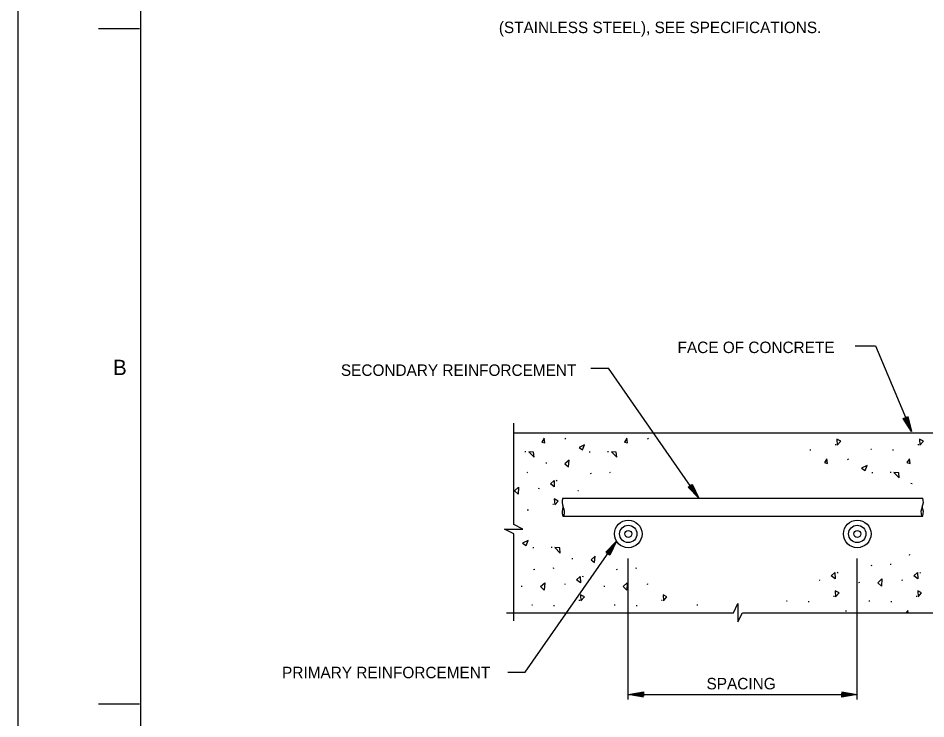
# Model space of a CAD drawing. Extents: x 22369.62 to 22373.29, y 22369.62 to 22372.46.
# Drawn here: x 22369.621 to 22370.546, y 22370.335 to 22371.049 of the extents above; entities that cross this region are included whole.
import ezdxf

# ---------------------------------------------------------------- set-up
doc = ezdxf.new("R2010")
doc.units = 0
for name, color, linetype in [('Default', 7, 'Continuous'), ('Level 1', 7, 'Continuous'), ('Level 10', 7, 'Continuous'), ('Level 2', 7, 'Continuous'), ('Level 22', 7, 'Continuous'), ('Level 4', 7, 'Continuous'), ('Level 7', 7, 'Continuous'), ('Level 8', 7, 'Continuous'), ('Level 9', 7, 'Continuous')]:
    doc.layers.add(name, color=color, linetype=linetype)

msp = doc.modelspace()

# ---------------------------------------------------------------- linework, layer by layer
at = {"layer": 'Default'}
for p, q in [((22370.1793, 22370.62059), (22370.1783, 22370.62009)), ((22370.26346, 22370.62059), (22370.26246, 22370.62009)), ((22370.42905, 22370.6087), (22370.42792, 22370.6087)), ((22370.45469, 22370.61428), (22370.45386, 22370.61434)), ((22370.4908, 22370.6094), (22370.48996, 22370.60955)), ((22370.51321, 22370.6087), (22370.51209, 22370.6087)), ((22370.53886, 22370.61428), (22370.53803, 22370.61434)), ((22370.13871, 22370.60715), (22370.13765, 22370.60715)), ((22370.20421, 22370.60676), (22370.20309, 22370.60676)), ((22370.22288, 22370.60715), (22370.22182, 22370.60715)), ((22370.46721, 22370.59959), (22370.46621, 22370.59909)), ((22370.15992, 22370.59551), (22370.15884, 22370.5957)), ((22370.14036, 22370.58607), (22370.13955, 22370.58576)), ((22370.20511, 22370.58495), (22370.20398, 22370.58463)), ((22370.22453, 22370.58607), (22370.22371, 22370.58576)), ((22370.49213, 22370.58576), (22370.491, 22370.58576)), ((22370.5108, 22370.58615), (22370.50973, 22370.58615)), ((22370.17053, 22370.57724), (22370.16959, 22370.5778)), ((22370.532, 22370.57451), (22370.53092, 22370.5747)), ((22370.15238, 22370.56949), (22370.15148, 22370.5699)), ((22370.19236, 22370.56749), (22370.19144, 22370.5674)), ((22370.16678, 22370.5533), (22370.16594, 22370.55336)), ((22370.14113, 22370.54772), (22370.14, 22370.54772)), ((22370.14668, 22370.5092), (22370.14556, 22370.5092)), ((22370.16535, 22370.50959), (22370.16429, 22370.50959)), ((22370.18656, 22370.49795), (22370.18547, 22370.49813)), ((22370.5302, 22370.50194), (22370.52912, 22370.50212)), ((22370.16699, 22370.48851), (22370.16618, 22370.4882)), ((22370.25116, 22370.48851), (22370.25035, 22370.4882)), ((22370.49122, 22370.49137), (22370.4901, 22370.49106)), ((22370.51064, 22370.4925), (22370.50983, 22370.49219)), ((22370.14758, 22370.48738), (22370.14645, 22370.48707)), ((22370.19716, 22370.47968), (22370.19622, 22370.48024)), ((22370.23174, 22370.48738), (22370.23062, 22370.48707)), ((22370.45664, 22370.48366), (22370.4557, 22370.48423)), ((22370.54081, 22370.48366), (22370.53987, 22370.48423)), ((22370.13483, 22370.46993), (22370.13391, 22370.46984)), ((22370.17901, 22370.47193), (22370.17812, 22370.47234)), ((22370.21899, 22370.46993), (22370.21808, 22370.46984)), ((22370.26318, 22370.47193), (22370.26229, 22370.47234)), ((22370.43849, 22370.47591), (22370.4376, 22370.47633)), ((22370.47847, 22370.47391), (22370.47756, 22370.47383)), ((22370.52266, 22370.47591), (22370.52176, 22370.47633)), ((22370.19341, 22370.45574), (22370.19258, 22370.4558)), ((22370.27758, 22370.45574), (22370.27674, 22370.4558)), ((22370.40483, 22370.45485), (22370.40399, 22370.455)), ((22370.42724, 22370.45414), (22370.42612, 22370.45414)), ((22370.45289, 22370.45973), (22370.45206, 22370.45979)), ((22370.48899, 22370.45485), (22370.48816, 22370.455)), ((22370.51141, 22370.45414), (22370.51029, 22370.45414)), ((22370.53706, 22370.45973), (22370.53622, 22370.45979)), ((22370.14535, 22370.45086), (22370.14451, 22370.45101)), ((22370.16776, 22370.45015), (22370.16664, 22370.45015)), ((22370.22951, 22370.45086), (22370.22868, 22370.45101)), ((22370.25193, 22370.45015), (22370.25081, 22370.45015)), ((22370.31368, 22370.45086), (22370.31285, 22370.45101)), ((22370.46541, 22370.44504), (22370.46441, 22370.44454))]:
    msp.add_line(p, q, dxfattribs=at)
for points in [[(22370.15796, 22370.61636), (22370.15738, 22370.62093), (22370.15482, 22370.61711)], [(22370.24213, 22370.61636), (22370.24155, 22370.62093), (22370.23898, 22370.61711)], [(22370.4559, 22370.61399), (22370.45946, 22370.61799), (22370.45548, 22370.62011)], [(22370.54007, 22370.61399), (22370.54363, 22370.61799), (22370.53965, 22370.62011)], [(22370.19634, 22370.6092), (22370.19832, 22370.6143), (22370.1928, 22370.61161)], [(22370.14653, 22370.60688), (22370.14153, 22370.60715), (22370.14694, 22370.60161)], [(22370.23069, 22370.60688), (22370.22569, 22370.60715), (22370.23111, 22370.60161)], [(22370.44588, 22370.59536), (22370.4453, 22370.59993), (22370.44273, 22370.59611)], [(22370.53005, 22370.59536), (22370.52946, 22370.59993), (22370.5269, 22370.59611)], [(22370.18267, 22370.59851), (22370.1784, 22370.59478), (22370.18194, 22370.5918)], [(22370.48425, 22370.5882), (22370.48623, 22370.5933), (22370.48071, 22370.59061)], [(22370.51861, 22370.58588), (22370.51361, 22370.58615), (22370.51903, 22370.58061)], [(22370.16757, 22370.57134), (22370.16357, 22370.57436), (22370.1674, 22370.57776)], [(22370.13071, 22370.56382), (22370.12686, 22370.56738), (22370.13113, 22370.5712)], [(22370.16798, 22370.55301), (22370.17155, 22370.55701), (22370.16757, 22370.55913)], [(22370.13881, 22370.51163), (22370.14079, 22370.51674), (22370.13526, 22370.51405)], [(22370.17316, 22370.50932), (22370.16816, 22370.50959), (22370.17358, 22370.50405)], [(22370.20931, 22370.50095), (22370.20504, 22370.49722), (22370.20858, 22370.49424)], [(22370.1942, 22370.47378), (22370.1902, 22370.4768), (22370.19404, 22370.4802)], [(22370.45368, 22370.47777), (22370.44968, 22370.48079), (22370.45351, 22370.48419)], [(22370.53785, 22370.47777), (22370.53385, 22370.48079), (22370.53768, 22370.48419)], [(22370.15735, 22370.46626), (22370.15349, 22370.46982), (22370.15776, 22370.47363)], [(22370.24151, 22370.46626), (22370.23766, 22370.46982), (22370.24193, 22370.47363)], [(22370.50099, 22370.47025), (22370.49714, 22370.47381), (22370.50141, 22370.47762)], [(22370.19462, 22370.45545), (22370.19818, 22370.45945), (22370.1942, 22370.46157)], [(22370.27879, 22370.45545), (22370.28235, 22370.45945), (22370.27837, 22370.46157)], [(22370.4541, 22370.45944), (22370.45766, 22370.46344), (22370.45368, 22370.46556)], [(22370.53826, 22370.45944), (22370.54183, 22370.46344), (22370.53785, 22370.46556)]]:
    msp.add_lwpolyline(points, close=True, dxfattribs=at)
msp.add_lwpolyline([(22370.52795, 22370.44308), (22370.52766, 22370.44537), (22370.52612, 22370.44308)], dxfattribs=at)
at = {"layer": 'Level 1'}
for p, q in [((22370.12621, 22370.53298), (22370.12621, 22370.63628)), ((22370.12621, 22370.52363), (22370.11684, 22370.52829)), ((22370.11684, 22370.52829), (22370.13557, 22370.52829)), ((22370.13557, 22370.52829), (22370.12621, 22370.53298)), ((22370.12621, 22370.43486), (22370.12621, 22370.52363)), ((22370.24288, 22370.35468), (22370.24288, 22370.49852)), ((22370.47621, 22370.35468), (22370.47621, 22370.49852)), ((22370.35003, 22370.44322), (22370.35468, 22370.45259)), ((22370.35468, 22370.45259), (22370.35468, 22370.43386)), ((22370.11893, 22370.44322), (22370.35003, 22370.44322)), ((22370.35468, 22370.43386), (22370.35937, 22370.44322)), ((22370.35937, 22370.44322), (22370.6021, 22370.44322)), ((22370.24288, 22370.35988), (22370.47621, 22370.35988))]:
    msp.add_line(p, q, dxfattribs=at)
msp.add_lwpolyline([(22369.6213, 22372.4553), (22373.288, 22372.4553), (22373.288, 22369.6213), (22369.6213, 22369.6213)], close=True, dxfattribs=at)
at = {"layer": 'Level 10'}
for p, q in [((22369.703, 22371.0383), (22369.745, 22371.0383)), ((22370.12621, 22370.62655), (22370.59288, 22370.62655)), ((22369.703, 22370.3503), (22369.745, 22370.3503))]:
    msp.add_line(p, q, dxfattribs=at)
at = {"layer": 'Level 2'}
for p, q in [((22370.20489, 22370.69224), (22370.2228, 22370.69224)), ((22370.3149, 22370.55988), (22370.2228, 22370.69224)), ((22370.13803, 22370.38262), (22370.23091, 22370.51611)), ((22370.12012, 22370.38262), (22370.13803, 22370.38262))]:
    msp.add_line(p, q, dxfattribs=at)
for points in [[(22370.47403, 22370.71506), (22370.49485, 22370.71506), (22370.53159, 22370.62777)], [(22370.52792, 22370.64313), (22370.53159, 22370.62777), (22370.52316, 22370.64113), (22370.52723, 22370.64284), (22370.52991, 22370.63176), (22370.52419, 22370.64084), (22370.5268, 22370.64194), (22370.52829, 22370.6356), (22370.52521, 22370.64055), (22370.52629, 22370.641), (22370.52661, 22370.6396)], [(22370.30812, 22370.57415), (22370.3149, 22370.55988), (22370.30388, 22370.5712), (22370.3075, 22370.57372), (22370.31242, 22370.56344), (22370.30494, 22370.57112), (22370.30726, 22370.57275), (22370.31005, 22370.56686), (22370.306, 22370.57106), (22370.30696, 22370.57173), (22370.30757, 22370.57041)], [(22370.21989, 22370.5048), (22370.23091, 22370.51611), (22370.22413, 22370.50184), (22370.2205, 22370.50437), (22370.22843, 22370.51256), (22370.22383, 22370.50287), (22370.2215, 22370.50449), (22370.22606, 22370.50913), (22370.22353, 22370.50389), (22370.22257, 22370.50456), (22370.22358, 22370.50558)], [(22370.25846, 22370.3573), (22370.24288, 22370.35988), (22370.25846, 22370.36247), (22370.25846, 22370.35805), (22370.24721, 22370.35988), (22370.2578, 22370.36163), (22370.2578, 22370.3588), (22370.25138, 22370.35988), (22370.25713, 22370.3608), (22370.25713, 22370.35963), (22370.25571, 22370.35988)], [(22370.46063, 22370.36247), (22370.47621, 22370.35988), (22370.46063, 22370.3573), (22370.46063, 22370.36172), (22370.47188, 22370.35988), (22370.4613, 22370.35813), (22370.4613, 22370.36097), (22370.46771, 22370.35988), (22370.46196, 22370.35897), (22370.46196, 22370.36013), (22370.46338, 22370.35988)]]:
    msp.add_lwpolyline(points, dxfattribs=at)
at = {"layer": 'Level 22'}
for centre, radius in [((22370.24288, 22370.52349), 0.01406), ((22370.47621, 22370.52349), 0.01406), ((22370.24288, 22370.52349), 0.00879), ((22370.24288, 22370.52349), 0.00352), ((22370.47621, 22370.52349), 0.00879), ((22370.47621, 22370.52349), 0.00352)]:
    msp.add_circle(centre, radius, dxfattribs=at)
at = {"layer": 'Level 7'}
for p, q in [((22370.17621, 22370.55988), (22370.54288, 22370.55988)), ((22370.17675, 22370.54155), (22370.54288, 22370.54155))]:
    msp.add_line(p, q, dxfattribs=at)
for centre, radius, start, end in [((22370.18685, 22370.55597), 0.01133, 159.80812, 206.60705), ((22370.53225, 22370.55597), 0.01133, 333.39295, 20.19188), ((22370.18685, 22370.54582), 0.01133, 153.39295, 200.19356), ((22370.16662, 22370.54582), 0.01133, 339.80644, 26.60705), ((22370.55247, 22370.54582), 0.01133, 153.39295, 200.19356), ((22370.53225, 22370.54582), 0.01133, 339.80644, 26.60705), ((22370.17673, 22370.5421), 0.000555, 200.19356, 339.80644), ((22370.54236, 22370.5421), 0.000555, 200.19356, 339.80644)]:
    msp.add_arc(centre, radius, start, end, dxfattribs=at)
at = {"layer": 'Level 8'}
for p, q in [((22370.52991, 22370.63176), (22370.52991, 22370.63176)), ((22370.53159, 22370.62777), (22370.53159, 22370.62777)), ((22370.31242, 22370.56344), (22370.31242, 22370.56344)), ((22370.3149, 22370.55988), (22370.3149, 22370.55988)), ((22370.23091, 22370.51611), (22370.23091, 22370.51611)), ((22370.22843, 22370.51256), (22370.22843, 22370.51256)), ((22370.24288, 22370.35988), (22370.24288, 22370.35988)), ((22370.24721, 22370.35988), (22370.24721, 22370.35988)), ((22370.47188, 22370.35988), (22370.47188, 22370.35988)), ((22370.47621, 22370.35988), (22370.47621, 22370.35988))]:
    msp.add_line(p, q, dxfattribs=at)
at = {"layer": 'Level 9'}
msp.add_line((22369.7463, 22369.6633), (22369.7463, 22372.4133), dxfattribs=at)

# ---------------------------------------------------------------- texts
at = {"layer": 'Level 1'}
msp.add_text('B', height=0.01561, dxfattribs=at).set_placement((22369.718, 22370.6853))
at = {"layer": 'Level 4'}
for s, height, p in [('(STAINLESS STEEL), SEE SPECIFICATIONS.', 0.0116667, (22370.11107, 22371.03368)), ('FACE OF CONCRETE', 0.0116979, (22370.29314, 22370.7077)), ('SECONDARY REINFORCEMENT', 0.0116979, (22369.95012, 22370.68447)), ('PRIMARY REINFORCEMENT', 0.0116979, (22369.89021, 22370.37648)), ('SPACING', 0.011698, (22370.32267, 22370.36514))]:
    msp.add_text(s, height=height, dxfattribs=at).set_placement(p)

doc.saveas('drawing.dxf')
